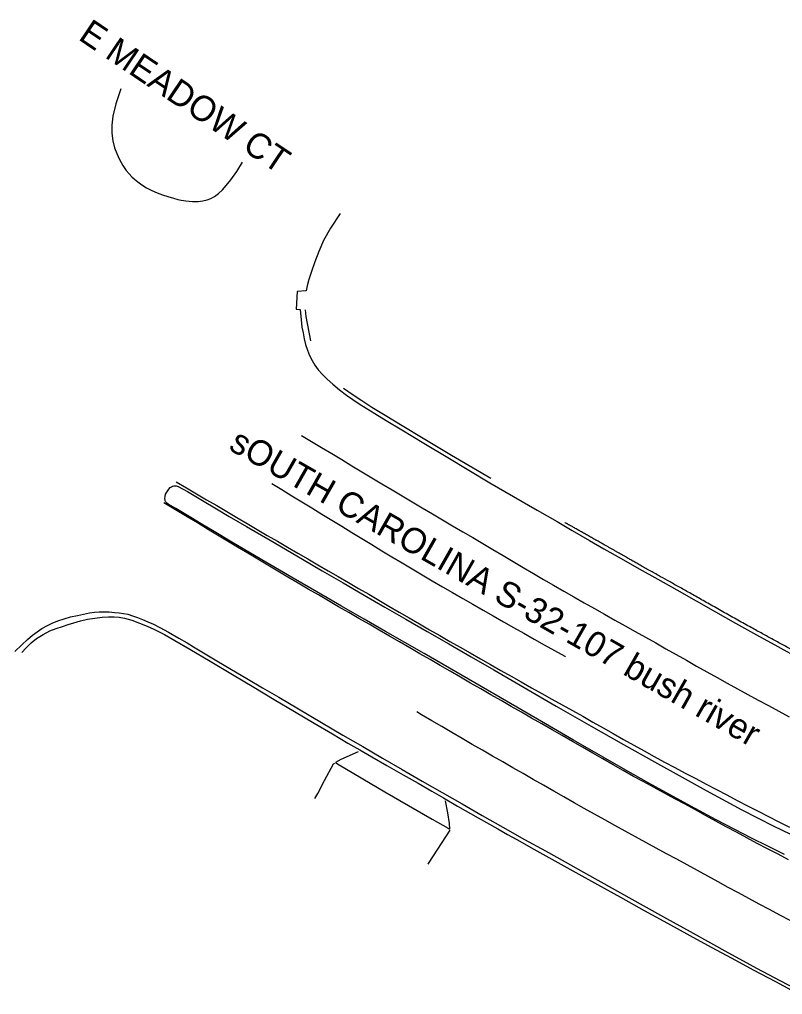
# Model space of a CAD drawing. Extents: x 1961683 to 1977751, y 798292 to 805767.
# Drawn here: x 1962372.5 to 1962535.1, y 800132.6 to 800340.3 of the extents above; entities that cross this region are included whole.
import ezdxf

# ---------------------------------------------------------------- set-up
doc = ezdxf.new("R2010")
doc.units = 0
for name, color, linetype in [('RD_EX_Conc', 7, 'Continuous'), ('RD_EX_Road', 7, 'Continuous'), ('RD_EX_Road_Paint', 7, 'Continuous'), ('RD_TX_RoadID', 7, 'Continuous')]:
    doc.layers.add(name, color=color, linetype=linetype)

msp = doc.modelspace()

# ---------------------------------------------------------------- linework, layer by layer
at = {"layer": 'RD_EX_Conc'}
for points in [[(1962394.08, 800325.53), (1962393, 800322.33), (1962392.39, 800319.77), (1962392.17, 800317.84), (1962392.16, 800316.09), (1962392.34, 800314.46), (1962392.69, 800313.02), (1962393.18, 800311.75), (1962393.8, 800310.48), (1962394.52, 800309.21), (1962395.2, 800308.19), (1962395.81, 800307.43), (1962396.39, 800306.81), (1962396.97, 800306.29), (1962397.68, 800305.72), (1962398.53, 800305.1), (1962399.54, 800304.48), (1962400.67, 800303.87), (1962401.8, 800303.37), (1962402.91, 800302.97), (1962404.08, 800302.59), (1962405.27, 800302.24), (1962406.19, 800301.98), (1962406.89, 800301.83), (1962407.93, 800301.69), (1962409.32, 800301.58), (1962410.54, 800301.57), (1962411.54, 800301.68), (1962412.43, 800301.88), (1962413.23, 800302.17), (1962414.05, 800302.64), (1962414.89, 800303.29), (1962415.72, 800304.06), (1962416.54, 800304.97), (1962417.51, 800306.2), (1962418.76, 800307.95), (1962420.02, 800309.93)], [(1962535.54, 800162.42), (1962531.96, 800164.17), (1962528.51, 800165.89), (1962524.94, 800167.7), (1962520.93, 800169.8), (1962516.45, 800172.2), (1962511.64, 800174.82), (1962506.59, 800177.61), (1962501.71, 800180.37), (1962496.83, 800183.17), (1962490.57, 800186.78), (1962482.9, 800191.21), (1962474.9, 800195.84), (1962466.78, 800200.53), (1962458.7, 800205.2), (1962450.49, 800209.92), (1962445.96, 800212.53), (1962441.07, 800215.34), (1962435.84, 800218.35), (1962430.79, 800221.26), (1962422.92, 800225.87), (1962417.75, 800228.98), (1962413.95, 800231.25), (1962411.2, 800232.88), (1962408.98, 800234.2), (1962407.2, 800235.28), (1962405.81, 800236.1), (1962404.79, 800236.69), (1962404.14, 800237.08), (1962403.82, 800237.31), (1962403.71, 800237.42), (1962403.62, 800237.53), (1962403.56, 800237.65), (1962403.52, 800237.78), (1962403.49, 800237.93), (1962403.46, 800238.28), (1962403.5, 800238.7), (1962403.59, 800239.21), (1962404.3, 800240.25), (1962404.6, 800240.58), (1962404.86, 800240.77), (1962405.1, 800240.87), (1962405.35, 800240.94), (1962405.59, 800240.97), (1962405.83, 800240.97), (1962406.26, 800240.82), (1962408.24, 800239.77), (1962411.47, 800237.87), (1962414.46, 800236.09), (1962417.17, 800234.46), (1962420.87, 800232.27), (1962425.86, 800229.35), (1962432.77, 800225.32), (1962436.98, 800222.87), (1962441.44, 800220.28), (1962445.9, 800217.69), (1962450.36, 800215.12), (1962454.82, 800212.55), (1962459.33, 800209.95), (1962463.96, 800207.28), (1962468.7, 800204.54), (1962473.55, 800201.72), (1962478.3, 800198.97), (1962486.86, 800194.02), (1962494.28, 800189.76), (1962501.23, 800185.82), (1962507.8, 800182.14), (1962513.68, 800178.87), (1962518.81, 800176.04), (1962523.04, 800173.75), (1962526.45, 800171.95), (1962529.76, 800170.24), (1962533.13, 800168.52), (1962536.78, 800166.72)]]:
    msp.add_lwpolyline(points, dxfattribs=at)
at = {"layer": 'RD_EX_Road'}
for points in [[(1962440.78, 800298.99), (1962438.72, 800295.86), (1962437.29, 800293.22), (1962436.27, 800290.89), (1962435.41, 800288.67), (1962434.71, 800286.65), (1962434.16, 800284.96), (1962433.78, 800283.58), (1962433.58, 800282.51), (1962431.62, 800282.38), (1962431.4, 800278.63), (1962432.28, 800278.52), (1962432.48, 800276.33), (1962432.67, 800274.77), (1962432.89, 800273.54), (1962433.13, 800272.32), (1962433.44, 800271.1), (1962433.82, 800269.9), (1962434.28, 800268.75), (1962434.81, 800267.68), (1962435.42, 800266.67), (1962436.15, 800265.69), (1962437.01, 800264.71), (1962438.03, 800263.69), (1962439.24, 800262.6), (1962440.68, 800261.43), (1962442.17, 800260.29), (1962443.53, 800259.34), (1962444.89, 800258.45), (1962446.37, 800257.5), (1962448.2, 800256.36), (1962450.58, 800254.91), (1962453.93, 800252.89), (1962458.65, 800250.06), (1962463.74, 800247), (1962468.22, 800244.3), (1962472.69, 800241.63), (1962477.77, 800238.69), (1962482.78, 800235.81), (1962487.03, 800233.34), (1962490.23, 800231.47), (1962492.11, 800230.37), (1962493.94, 800229.32), (1962497, 800227.57), (1962500.73, 800225.45), (1962504.57, 800223.28), (1962508.52, 800221.05), (1962512.56, 800218.79), (1962516.67, 800216.49), (1962520.83, 800214.14), (1962525.09, 800211.73), (1962529.51, 800209.24), (1962534.06, 800206.69), (1962538.73, 800204.14)], [(1962434.58, 800271.89), (1962433.54, 800277.06), (1962433.42, 800278.44)], [(1962472.94, 800242.49), (1962464.53, 800247.44), (1962458.47, 800251.06), (1962454.01, 800253.75), (1962450.38, 800255.93), (1962447.53, 800257.68), (1962445.41, 800259.05), (1962443.55, 800260.31), (1962441.52, 800261.73)], [(1962371.5, 800205.66), (1962372.95, 800207.09), (1962374.16, 800208.23), (1962375.24, 800209.11), (1962376.25, 800209.87), (1962377.24, 800210.55), (1962378.3, 800211.15), (1962379.45, 800211.68), (1962380.67, 800212.17), (1962381.97, 800212.62), (1962383.36, 800213.01), (1962384.8, 800213.35), (1962386.14, 800213.63), (1962387.36, 800213.87), (1962388.45, 800214.03), (1962389.44, 800214.11), (1962390.49, 800214.13), (1962391.61, 800214.08), (1962392.68, 800214), (1962393.68, 800213.9), (1962394.63, 800213.76), (1962395.53, 800213.58), (1962396.52, 800213.29), (1962397.59, 800212.91), (1962398.69, 800212.48), (1962399.81, 800212.01), (1962401.02, 800211.45), (1962402.39, 800210.75), (1962404.22, 800209.75), (1962406.42, 800208.51), (1962408.2, 800207.48), (1962409.58, 800206.63), (1962411.65, 800205.38), (1962414.5, 800203.68), (1962417.63, 800201.83), (1962420.93, 800199.88), (1962424.27, 800197.92), (1962427.74, 800195.91), (1962431.93, 800193.44), (1962436.81, 800190.55), (1962441.41, 800187.85), (1962445.64, 800185.39), (1962449.83, 800182.96), (1962454.05, 800180.51), (1962458.28, 800178.06), (1962462.52, 800175.62), (1962466.78, 800173.18), (1962471.05, 800170.73), (1962475.5, 800168.21), (1962480.09, 800165.63), (1962484.54, 800163.16), (1962488.77, 800160.81), (1962492.67, 800158.64), (1962496.34, 800156.59), (1962500.56, 800154.23), (1962505.37, 800151.55), (1962510.37, 800148.78), (1962515.38, 800146.01), (1962519.75, 800143.59), (1962523.43, 800141.55), (1962526.69, 800139.77), (1962529.58, 800138.2), (1962532.11, 800136.84), (1962534.52, 800135.57), (1962538.05, 800133.73)], [(1962372.95, 800205.43), (1962373.82, 800206.37), (1962374.95, 800207.48), (1962376.11, 800208.43), (1962377.5, 800209.3), (1962378.95, 800210.04), (1962380.31, 800210.58), (1962381.6, 800211.01), (1962382.81, 800211.41), (1962384.05, 800211.8), (1962385.44, 800212.18), (1962386.95, 800212.52), (1962388.55, 800212.77), (1962390.09, 800212.94), (1962391.44, 800213.04), (1962392.62, 800213.06), (1962393.69, 800212.96), (1962394.88, 800212.73), (1962396.39, 800212.3), (1962398.06, 800211.72), (1962399.67, 800211.04), (1962401.08, 800210.4), (1962402.09, 800209.93), (1962403.35, 800209.26), (1962405.54, 800208.03), (1962408.74, 800206.17), (1962413.09, 800203.6), (1962417.86, 800200.76), (1962422.38, 800198.07), (1962426.75, 800195.46), (1962431.11, 800192.87), (1962435.3, 800190.38), (1962439.17, 800188.1), (1962442.48, 800186.15), (1962445.03, 800184.68), (1962447.55, 800183.24), (1962450.79, 800181.39), (1962454.25, 800179.4), (1962457.45, 800177.58), (1962460.32, 800175.93), (1962462.81, 800174.47), (1962465.82, 800172.72), (1962470.25, 800170.19), (1962474.38, 800167.86), (1962476.49, 800166.66), (1962478.44, 800165.57), (1962482.08, 800163.55), (1962486.56, 800161.05), (1962491.04, 800158.57), (1962495.66, 800156.01), (1962500.57, 800153.29), (1962505.59, 800150.5), (1962510.56, 800147.75), (1962515.36, 800145.11), (1962519.89, 800142.66), (1962524.32, 800140.28), (1962528.84, 800137.85), (1962533.59, 800135.31), (1962538.73, 800132.57)], [(1962444.68, 800184.25), (1962440.95, 800182.63), (1962439.84, 800181.98), (1962440.58, 800181.53), (1962450.31, 800175.73), (1962460.41, 800169.91), (1962463.82, 800168.01), (1962464.21, 800167.8), (1962464.12, 800168.97), (1962463.75, 800171.27), (1962463.26, 800173.84)], [(1962435.43, 800174.36), (1962436.02, 800175.38), (1962437.5, 800178.15), (1962439.38, 800181.71), (1962439.68, 800181.89)], [(1962459.57, 800160.36), (1962459.77, 800160.66), (1962464.22, 800167.61)]]:
    msp.add_lwpolyline(points, dxfattribs=at)
msp.add_open_spline([(1962666.93, 800138.79), (1962660.87, 800141.73), (1962650.34, 800146.87), (1962638.34, 800152.89), (1962624.46, 800159.82), (1962618.96, 800162.62), (1962616.17, 800164.01), (1962614.42, 800164.88), (1962609.09, 800167.73), (1962604.18, 800170.21), (1962595.45, 800174.62), (1962585.94, 800179.63), (1962568.57, 800188.82), (1962559.82, 800193.64), (1962552.62, 800197.56), (1962541.22, 800203.78), (1962528.49, 800210.68), (1962514.22, 800218.75), (1962504.91, 800223.93), (1962499.33, 800227.16), (1962491.18, 800231.72), (1962488.71, 800233.14)], degree=2, dxfattribs=at)
at = {"layer": 'RD_EX_Road_Paint'}
for points in [[(1962432.58, 800251.7), (1962434.72, 800250.41), (1962436.86, 800249.12), (1962439.01, 800247.83), (1962441.15, 800246.54), (1962443.29, 800245.25), (1962445.43, 800243.97), (1962447.57, 800242.68), (1962449.71, 800241.39), (1962451.86, 800240.1), (1962454, 800238.81), (1962456.15, 800237.54), (1962458.31, 800236.27), (1962460.46, 800235), (1962462.61, 800233.73), (1962464.77, 800232.46), (1962466.92, 800231.19), (1962469.07, 800229.92), (1962471.23, 800228.65), (1962473.38, 800227.38), (1962475.53, 800226.11), (1962477.69, 800224.84), (1962479.84, 800223.57), (1962481.99, 800222.3), (1962484.15, 800221.03), (1962486.3, 800219.76), (1962488.46, 800218.5), (1962490.64, 800217.28), (1962492.82, 800216.05), (1962495, 800214.82), (1962497.17, 800213.6), (1962499.35, 800212.37), (1962501.53, 800211.14), (1962503.71, 800209.92), (1962505.89, 800208.69), (1962508.07, 800207.47), (1962510.25, 800206.24), (1962512.42, 800205.01), (1962514.6, 800203.79), (1962516.78, 800202.56), (1962518.96, 800201.34), (1962521.14, 800200.11), (1962523.32, 800198.89), (1962525.52, 800197.69), (1962527.71, 800196.5), (1962529.91, 800195.31), (1962532.11, 800194.12), (1962534.31, 800192.92), (1962536.5, 800191.73)], [(1962405.88, 800241.81), (1962408.04, 800240.54), (1962410.19, 800239.27), (1962412.35, 800238.01), (1962414.5, 800236.74), (1962416.66, 800235.47), (1962418.81, 800234.21), (1962420.97, 800232.94), (1962423.12, 800231.67), (1962425.28, 800230.41), (1962427.44, 800229.15), (1962429.6, 800227.89), (1962431.76, 800226.63), (1962433.92, 800225.37), (1962436.08, 800224.12), (1962438.24, 800222.87), (1962440.41, 800221.61), (1962442.57, 800220.36), (1962444.73, 800219.1), (1962446.89, 800217.84), (1962449.04, 800216.58), (1962451.2, 800215.32), (1962453.37, 800214.06), (1962455.53, 800212.81), (1962457.7, 800211.56), (1962459.86, 800210.31), (1962462.03, 800209.06), (1962464.2, 800207.82), (1962466.36, 800206.58), (1962468.54, 800205.34), (1962470.71, 800204.1), (1962472.88, 800202.87), (1962475.06, 800201.64), (1962477.24, 800200.41), (1962479.41, 800199.18), (1962481.59, 800197.95), (1962483.77, 800196.72), (1962485.95, 800195.5), (1962488.13, 800194.28), (1962490.31, 800193.06), (1962492.5, 800191.85), (1962494.68, 800190.63), (1962496.86, 800189.4), (1962499.03, 800188.17), (1962501.21, 800186.93), (1962503.38, 800185.7), (1962505.57, 800184.49), (1962507.76, 800183.29), (1962509.96, 800182.1), (1962512.16, 800180.91), (1962514.37, 800179.73), (1962516.58, 800178.57), (1962518.79, 800177.41), (1962521.01, 800176.25), (1962523.22, 800175.09), (1962525.43, 800173.93), (1962527.65, 800172.76), (1962529.87, 800171.61), (1962532.09, 800170.47), (1962534.32, 800169.34), (1962536.55, 800168.21)], [(1962426.25, 800241.46), (1962428.38, 800240.16), (1962430.51, 800238.86), (1962432.65, 800237.55), (1962434.78, 800236.25), (1962436.91, 800234.95), (1962439.05, 800233.64), (1962441.18, 800232.34), (1962443.31, 800231.03), (1962445.44, 800229.73), (1962447.58, 800228.43), (1962449.71, 800227.12), (1962451.85, 800225.83), (1962454, 800224.55), (1962456.15, 800223.27), (1962458.29, 800221.99), (1962460.44, 800220.72), (1962462.6, 800219.45), (1962464.76, 800218.2), (1962466.93, 800216.96), (1962469.1, 800215.71), (1962471.27, 800214.47), (1962473.44, 800213.23), (1962475.61, 800211.98), (1962477.78, 800210.75), (1962479.96, 800209.53), (1962482.14, 800208.3), (1962484.32, 800207.08), (1962486.5, 800205.85), (1962488.68, 800204.63), (1962488.83, 800204.55)], [(1962536.35, 800161.29), (1962534.13, 800162.44), (1962531.91, 800163.59), (1962529.71, 800164.77), (1962527.51, 800165.96), (1962525.31, 800167.15), (1962523.1, 800168.33), (1962520.9, 800169.52), (1962518.7, 800170.71), (1962516.51, 800171.9), (1962514.31, 800173.09), (1962512.11, 800174.28), (1962509.91, 800175.47), (1962507.71, 800176.66), (1962505.52, 800177.85), (1962503.32, 800179.04), (1962501.15, 800180.28), (1962498.98, 800181.52), (1962496.81, 800182.76), (1962494.64, 800184.01), (1962492.47, 800185.25), (1962490.3, 800186.49), (1962488.13, 800187.73), (1962485.96, 800188.97), (1962483.79, 800190.21), (1962481.62, 800191.46), (1962479.45, 800192.7), (1962477.28, 800193.95), (1962475.12, 800195.2), (1962472.95, 800196.45), (1962470.79, 800197.7), (1962468.62, 800198.94), (1962466.45, 800200.19), (1962464.29, 800201.44), (1962462.12, 800202.69), (1962459.96, 800203.94), (1962457.79, 800205.19), (1962455.63, 800206.44), (1962453.46, 800207.69), (1962451.3, 800208.94), (1962449.14, 800210.2), (1962446.97, 800211.45), (1962444.81, 800212.7), (1962442.65, 800213.96), (1962440.48, 800215.21), (1962438.32, 800216.46), (1962436.16, 800217.72), (1962433.99, 800218.97), (1962431.83, 800220.22), (1962429.68, 800221.49), (1962427.53, 800222.77), (1962425.39, 800224.06), (1962423.24, 800225.34), (1962421.1, 800226.63), (1962418.95, 800227.91), (1962416.81, 800229.2), (1962414.66, 800230.48), (1962412.52, 800231.76), (1962410.38, 800233.05), (1962408.23, 800234.33), (1962406.09, 800235.62), (1962403.94, 800236.9), (1962403.25, 800237.31)], [(1962536.75, 800148.32), (1962534.55, 800149.49), (1962532.34, 800150.67), (1962530.13, 800151.84), (1962527.93, 800153.02), (1962525.73, 800154.21), (1962523.53, 800155.4), (1962521.34, 800156.6), (1962519.14, 800157.79), (1962516.94, 800158.99), (1962514.75, 800160.18), (1962512.55, 800161.38), (1962510.36, 800162.57), (1962508.16, 800163.76), (1962505.96, 800164.96), (1962503.77, 800166.15), (1962501.57, 800167.35), (1962499.38, 800168.56), (1962497.2, 800169.78), (1962495.02, 800170.99), (1962492.83, 800172.21), (1962490.66, 800173.44), (1962488.49, 800174.69), (1962486.32, 800175.93), (1962484.15, 800177.17), (1962481.98, 800178.41), (1962479.81, 800179.65), (1962477.64, 800180.9), (1962475.47, 800182.14), (1962473.3, 800183.38), (1962471.13, 800184.62), (1962468.96, 800185.87), (1962466.79, 800187.11), (1962464.63, 800188.37), (1962462.48, 800189.64), (1962460.33, 800190.91), (1962458.17, 800192.17), (1962457.14, 800192.78)]]:
    msp.add_lwpolyline(points, dxfattribs=at)

# ---------------------------------------------------------------- texts
at = {"layer": 'RD_TX_RoadID'}
for s, rotation, p in [('E MEADOW CT', 326.0371, (1962384.78, 800336.19)), ('sOUTH CAROLINA S-32-107 bush river', 330.3105, (1962416.82, 800248.81))]:
    msp.add_text(s, height=5.4, rotation=rotation, dxfattribs=at).set_placement(p)

doc.saveas('drawing.dxf')
